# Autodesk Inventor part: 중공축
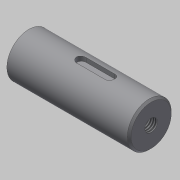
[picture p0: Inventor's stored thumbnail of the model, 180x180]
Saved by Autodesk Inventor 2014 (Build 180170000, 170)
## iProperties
Created: 2019-10
Part Number: 중공축
Material: 강철, 탄소
Document SubType Name: Modeling
Designer: mduedu
Density: 1 g/cm^3
Appearance: 기본값
Author: mduedu
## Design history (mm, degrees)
sketch "스케치1"
  geometry: L1 (0, 0)-(64, 0); L2 (64, 0)-(64, 11.5); L3 (64, 11.5)-(0, 11.5); L4 (0, 11.5)-(0, 0)
  constraints: 8 end point, 2 parallel, 1 horizontal, 1 perpendicular
  dimensions: "d0" = 64 distance of L2.end L3.end; "d2" = 23 diameter of L3 L1
revolve "회전1" sketch "스케치1" stored, may be unused: angle "d3" = 90 deg
hole "구멍1" diameter "d6" = 6.647; stored, may be unused: countersink angle "d10" = 90 deg, drill point angle "d12" = 118 deg; dims "d4" = 10, "d5" = 10, "d7" = 6, "d8" = 4, "d9" = 2, "d11" = 8
hole "구멍2" diameter "d15" = 13; stored, may be unused: countersink angle "d19" = 90 deg, drill point angle "d21" = 0 deg; dims "d13" = 10, "d14" = 10, "d16" = 6, "d17" = 15, "d18" = 20, "d20" = 32
sketch "스케치2"
  geometry: L1 (20, -7.5)-(20, -6.5) reference; L2 (20, -6.5)-(52, -6.5) reference; L3 (52, -6.5)-(52, -3.324) reference; L4 (52, -3.324)-(64, -3.324) reference; L5 (64, -3.324)-(64, -11.5) reference; L6 (64, -11.5)-(0, -11.5) reference; L7 (0, -11.5)-(0, -7.5) reference; L8 (0, -7.5)-(20, -7.5) reference; L9 (20, 6.5)-(20, 7.5) reference; L10 (20, 7.5)-(0, 7.5) reference; L11 (0, 7.5)-(0, 11.5) reference; L12 (0, 11.5)-(64, 11.5) reference; L13 (64, 11.5)-(64, 3.324) reference; L14 (64, 3.324)-(52, 3.324) reference; L15 (52, 3.324)-(52, 6.5) reference; L16 (52, 6.5)-(20, 6.5) reference; L17 (25, 11.5)-(45, 11.5); L18 (45, 11.5)-(45, 9); L19 (45, 9)-(25, 9); L20 (25, 9)-(25, 11.5); 1 further point
  constraints: 8 end point, 2 parallel, 1 horizontal, 1 perpendicular, 1 point on line
  dimensions: "d22" = 20 distance of L17.start L17.end; "d24" = 25 distance between parallel lines of L20 L11; "d25" = 2.5 distance of L17.end L18.end
extrude "돌출1" cut sketch "스케치2" stored distance "d26" = 5; taper "d27" = 0 deg
fillet "모깎기1"
fillet "모깎기2"
sketch "스케치3"
  geometry: 3 further points
  constraints: 2 vertical alignment, 1 other
hole "구멍3" sketch "스케치3" at (0, 7.5) diameter "d28" = 2.459; stored, may be unused: countersink angle "d32" = 90 deg, drill point angle "d34" = 118 deg; dims "d29" = 6, "d30" = 4, "d31" = 2, "d33" = 8
chamfer "모따기1" distance "d35" = 1; stored, may be unused: second distance "d36" = 2, angle "d37" = 45 deg
node "솔리드1"
node "절단 모서리 투영1"
